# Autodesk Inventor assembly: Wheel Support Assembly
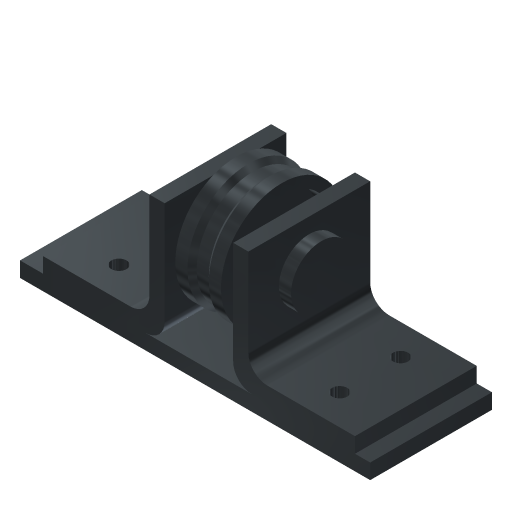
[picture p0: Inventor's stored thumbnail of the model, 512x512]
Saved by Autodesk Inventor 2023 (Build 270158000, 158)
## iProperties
Created: 2016-08
Part Number: Wheel Support Assembly
Document SubType Name: Assembly
Designer: Sandeep
Author: Sandeep
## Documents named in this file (5)
- D:\PROJECTS\Project 2022\Autodesk Inventor For Professional 2023\RESOURCES INVENTOR 2023\RESOURCES INVENTOR 2023\Inventor_2023_tut\Inventor_2023_tut\c15_Inv_2023_tut\c15_Inv_tut_2023\c15_tut03_inv\Wheel Support Assembly.iam
- D:\PROJECTS\Project 2022\Autodesk Inventor For Professional 2023\RESOURCES INVENTOR 2023\RESOURCES INVENTOR 2023\Inventor_2023_tut\Inventor_2023_tut\c15_Inv_2023_tut\c15_Inv_tut_2023\c15_tut03_inv\base.ipt
- D:\PROJECTS\Project 2022\Autodesk Inventor For Professional 2023\RESOURCES INVENTOR 2023\RESOURCES INVENTOR 2023\Inventor_2023_tut\Inventor_2023_tut\c15_Inv_2023_tut\c15_Inv_tut_2023\c15_tut03_inv\Support.ipt
- D:\PROJECTS\Project 2022\Autodesk Inventor For Professional 2023\RESOURCES INVENTOR 2023\RESOURCES INVENTOR 2023\Inventor_2023_tut\Inventor_2023_tut\c15_Inv_2023_tut\c15_Inv_tut_2023\c15_tut03_inv\Wheel.ipt
- D:\PROJECTS\Project 2022\Autodesk Inventor For Professional 2023\RESOURCES INVENTOR 2023\RESOURCES INVENTOR 2023\Inventor_2023_tut\Inventor_2023_tut\c15_Inv_2023_tut\c15_Inv_tut_2023\c15_tut03_inv\Shoulder screw.ipt
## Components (5 placed, 4 different names)
1. base:1 — Insert:1, Mate:1, Insert:2, Mate:2
2. Support:1 — Insert:1, Mate:1, Insert:3
3. Support:2 — Insert:2, Mate:2, Mate:3, Mate:4
4. Wheel:1 — Insert:3
5. Shoulder screw:1 — Mate:3, Mate:4
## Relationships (7: Mate 4, Insert 3)
- Insert:1: base:1 ↔ Support:1
- Mate:1: base:1 ↔ Support:1
- Insert:2: base:1 ↔ Support:2
- Mate:2: base:1 ↔ Support:2
- Insert:3: Support:1 ↔ Wheel:1
- Mate:3: Support:2 ↔ Shoulder screw:1
- Mate:4: Support:2 ↔ Shoulder screw:1
